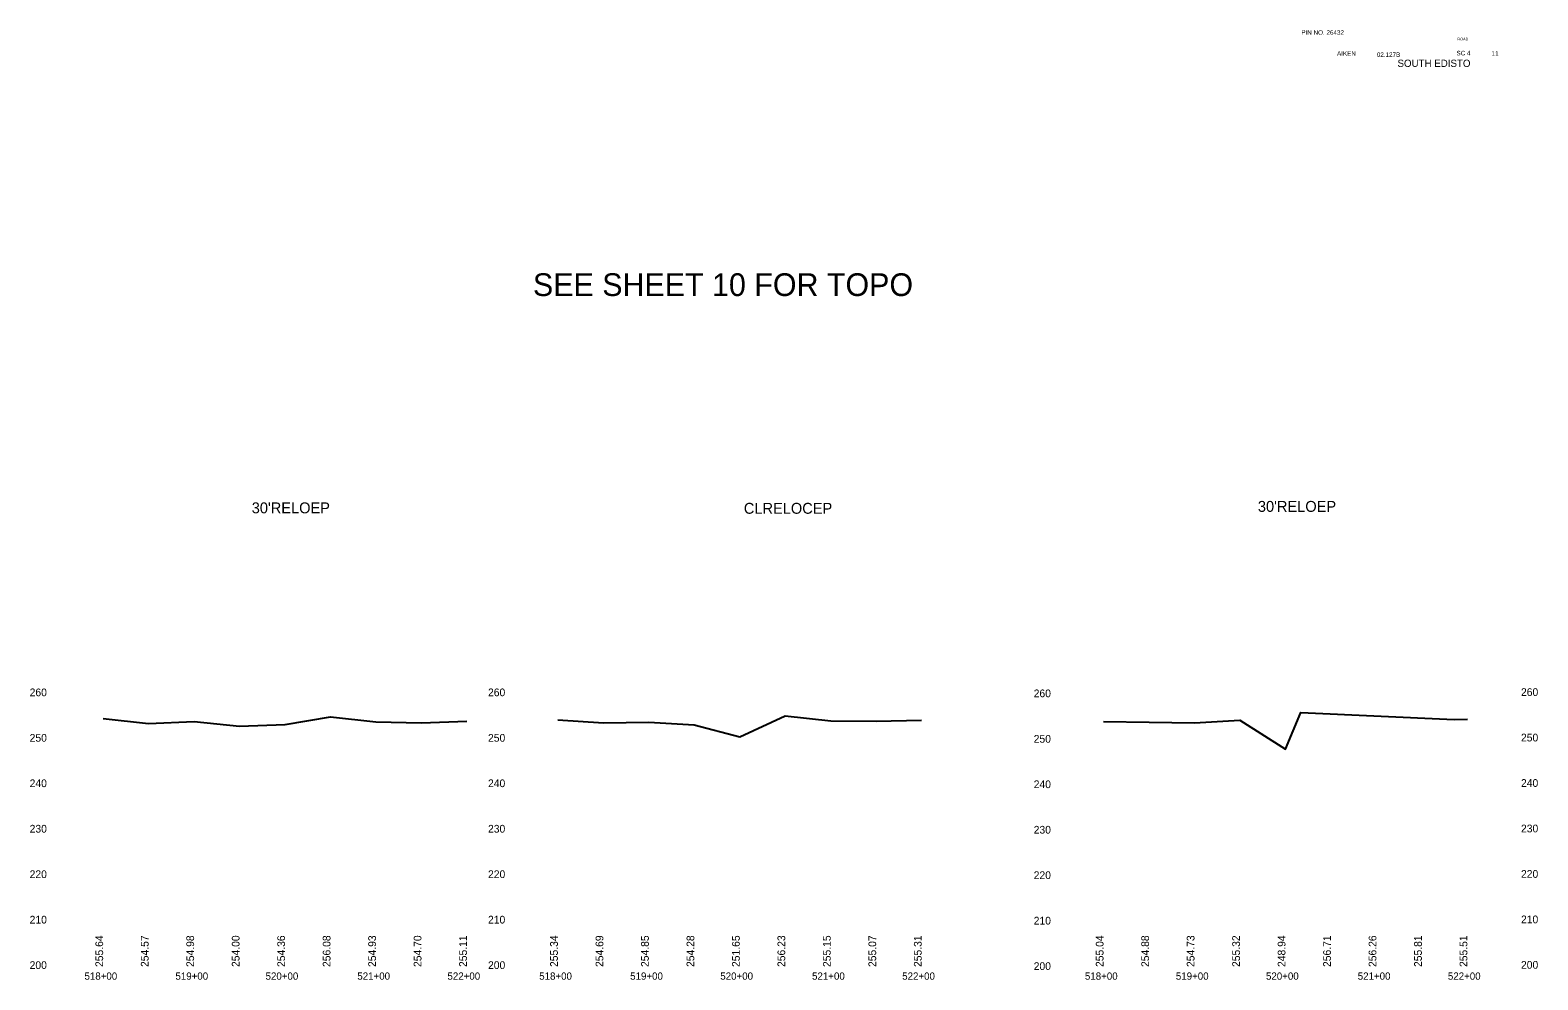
# Model space of a CAD drawing. Extents: x 49241 to 62599, y 49216 to 56011.
# Drawn here: x 50163 to 51821, y 54966 to 56011 of the extents above; entities that cross this region are included whole.
import ezdxf

# ---------------------------------------------------------------- set-up
doc = ezdxf.new("R2010")
doc.units = 0
for name, color, linetype in [('Level 24', 7, 'Continuous'), ('Level 25', 7, 'Continuous'), ('Level 40', 7, 'Continuous'), ('Level 42', 7, 'Continuous'), ('Level 43', 7, 'Continuous')]:
    doc.layers.add(name, color=color, linetype=linetype)

msp = doc.modelspace()

# ---------------------------------------------------------------- linework, layer by layer
at = {"layer": 'Level 40'}
for points in [[(50243.5, 55253.5), (50293.5, 55248.1), (50343.5, 55250.2), (50393.5, 55245.3), (50443.5, 55247.1), (50493.5, 55255.6), (50543.5, 55249.9), (50593.5, 55248.8), (50643.5, 55250.8)], [(50743.5, 55252), (50793.5, 55248.7), (50843.5, 55249.5), (50893.5, 55246.7), (50943.5, 55233.5), (50993.5, 55256.4), (51043.5, 55251), (51093.5, 55250.6), (51143.5, 55251.8)], [(51343.5, 55250.5), (51393.5, 55249.7), (51443.5, 55248.9), (51493.5, 55251.9), (51543.5, 55220), (51560.5, 55260.3), (51729.2, 55252.7), (51743.5, 55252.8)]]:
    msp.add_lwpolyline(points, dxfattribs=at)

# ---------------------------------------------------------------- texts
at = {"layer": 'Level 24'}
for s, height, p in [('PIN NO. 26432', 5, (51561, 56005.7)), ('ROAD', 3, (51732.6, 55999.4)), ('AIKEN', 5, (51600.2, 55982.6)), ('02.127B', 5, (51644, 55981.3)), ('SC 4', 5, (51731.6, 55983)), ('11', 5, (51770.2, 55982.6)), ('SOUTH EDISTO', 8, (51666.7, 55970.3))]:
    msp.add_text(s, height=height, dxfattribs=at).set_placement(p)
at = {"layer": 'Level 25'}
msp.add_text('SEE SHEET 10 FOR TOPO', height=25, dxfattribs=at).set_placement((50716.1, 55718.3))
at = {"layer": 'Level 42'}
for s, height, p in [('260', 8.5, (50162.7, 55278.1)), ('260', 8.5, (50666.7, 55278.1)), ('260', 8.5, (51802.5, 55278.4)), ('260', 8.5, (51266.7, 55277)), ('250', 8.5, (50162.7, 55228.1)), ('250', 8.5, (50666.7, 55228.1)), ('250', 8.5, (51802.5, 55228.4)), ('250', 8.5, (51266.7, 55227)), ('240', 8.5, (51802.5, 55178.4)), ('240', 8.5, (50162.7, 55178.1)), ('240', 8.5, (50666.7, 55178.1)), ('240', 8.5, (51266.7, 55177)), ('230', 8.5, (50162.7, 55128.1)), ('230', 8.5, (50666.7, 55128.1)), ('230', 8.5, (51266.7, 55127)), ('230', 8.5, (51802.5, 55128.4)), ('220', 8.5, (50162.7, 55078.1)), ('220', 8.5, (50666.7, 55078.1)), ('220', 8.5, (51266.7, 55077)), ('220', 8.5, (51802.5, 55078.4)), ('210', 8.5, (50162.7, 55028.1)), ('210', 8.5, (50666.7, 55028.1)), ('210', 8.5, (51266.7, 55027)), ('210', 8.5, (51802.5, 55028.4)), ('200', 8.5, (50162.7, 54978.1)), ('518+00', 8, (50223, 54966.3)), ('519+00', 8, (50323, 54966.3)), ('520+00', 8, (50422.1, 54966.3)), ('521+00', 8, (50523, 54966.3)), ('522+00', 8, (50622.1, 54966.3)), ('200', 8.5, (50666.7, 54978.1)), ('518+00', 8, (50723, 54966.3)), ('519+00', 8, (50823, 54966.3)), ('520+00', 8, (50922.1, 54966.3)), ('521+00', 8, (51023, 54966.3)), ('522+00', 8, (51122.1, 54966.3)), ('200', 8.5, (51266.7, 54977)), ('518+00', 8, (51323, 54966.3)), ('519+00', 8, (51423, 54966.3)), ('520+00', 8, (51522.1, 54966.3)), ('521+00', 8, (51623, 54966.3)), ('522+00', 8, (51722.1, 54966.3)), ('200', 8.5, (51802.5, 54978.4))]:
    msp.add_text(s, height=height, dxfattribs=at).set_placement(p)
at = {"layer": 'Level 43'}
for s, p in [("30'RELOEP", (50406.9, 55479.3)), ('CLRELOCEP', (50948, 55478.8)), ("30'RELOEP", (51513.2, 55480.9))]:
    msp.add_text(s, height=12, dxfattribs=at).set_placement(p)
for s, p in [('255.64', (50243.5, 54980.3)), ('254.57', (50293.5, 54980.3)), ('254.98', (50343.5, 54980.3)), ('254.00', (50393.5, 54980.3)), ('254.36', (50443.5, 54980.3)), ('256.08', (50493.5, 54980.3)), ('254.93', (50543.5, 54980.3)), ('254.70', (50593.5, 54980.3)), ('255.11', (50643.5, 54980.3)), ('255.34', (50743.5, 54980.3)), ('254.69', (50793.5, 54980.3)), ('254.85', (50843.5, 54980.3)), ('254.28', (50893.5, 54980.3)), ('251.65', (50943.5, 54980.3)), ('256.23', (50993.5, 54980.3)), ('255.15', (51043.5, 54980.3)), ('255.07', (51093.5, 54980.3)), ('255.31', (51143.5, 54980.3)), ('255.04', (51343.5, 54980.3)), ('254.88', (51393.5, 54980.3)), ('254.73', (51443.5, 54980.3)), ('255.32', (51493.5, 54980.3)), ('248.94', (51543.5, 54980.3)), ('256.71', (51593.5, 54980.3)), ('256.26', (51643.5, 54980.3)), ('255.81', (51693.5, 54980.3)), ('255.51', (51743.5, 54980.3))]:
    msp.add_text(s, height=8.5, rotation=90, dxfattribs=at).set_placement(p)

doc.saveas('drawing.dxf')
